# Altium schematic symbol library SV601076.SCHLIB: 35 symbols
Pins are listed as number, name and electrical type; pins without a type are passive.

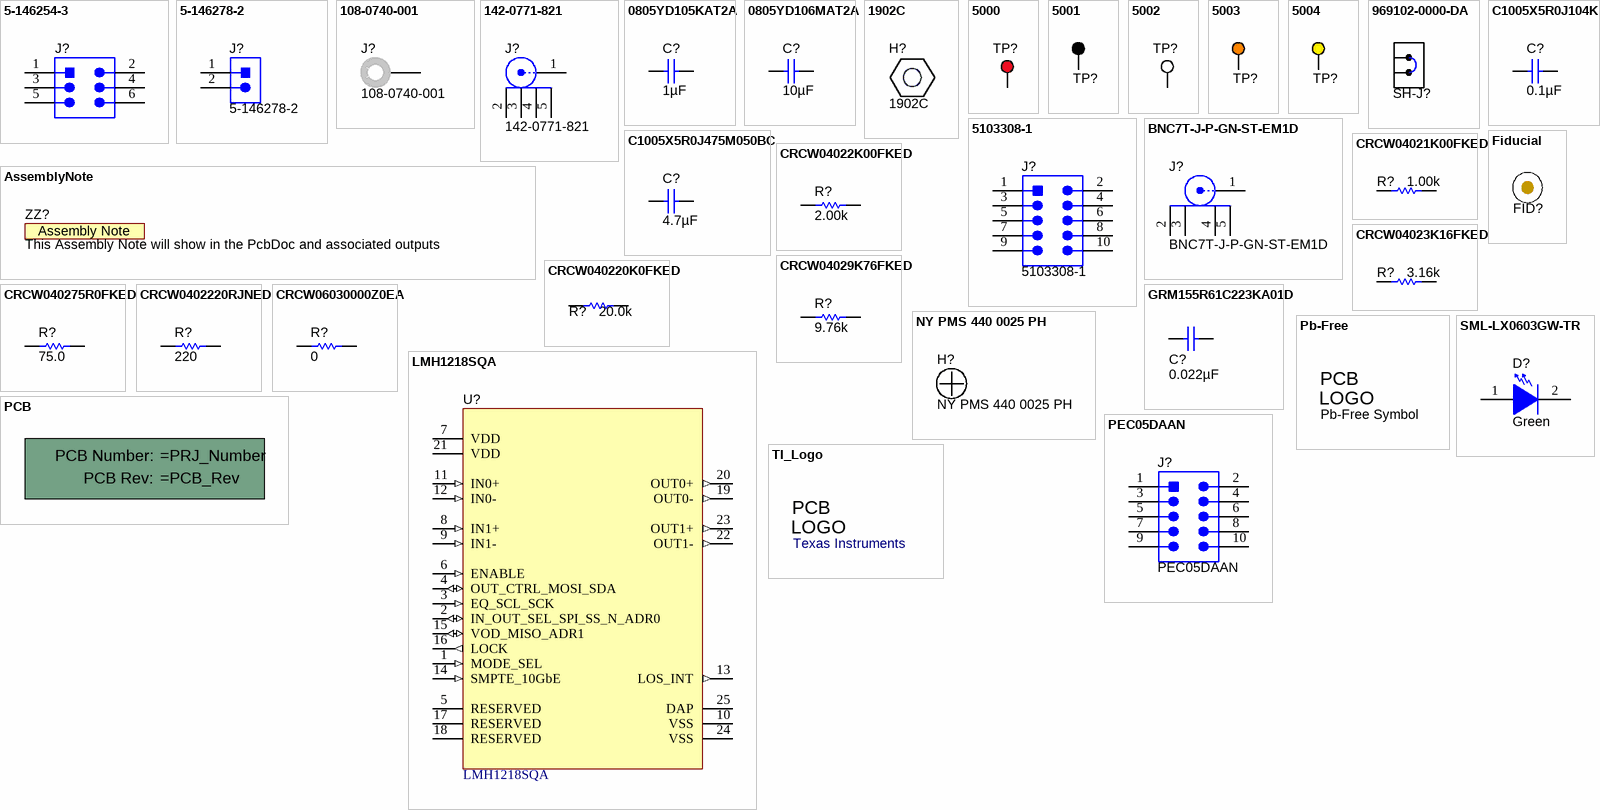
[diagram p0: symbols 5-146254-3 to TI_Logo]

## 5-146254-3
designator J?  (value not drawn)
Header, 100mil, 3x2, Tin, TH; Manufacturer: TE Connectivity; SymbolCreator: a0412235; U/M: EA
footprint TE_5-146254-3
pins: 1, 2, 3, 4, 5, 6

## 5-146278-2
designator J?
Header, 100mil, 2x1, Tin, TH; Manufacturer: TE Connectivity; SymbolCreator: a0412235; U/M: EA
footprint TE_5-146278-2
pins: 1, 2
1 alternate drawing of the same symbol

## 108-0740-001
designator J?
Standard Banana Jack, Uninsulated, 15A; Manufacturer: Emerson Network Power; SymbolCreator: a0412235; CompType: Connector; U/M: EA
footprint Johnson_108-0740-001
pins: 1

## 142-0771-821
designator J?
Connector, TH, End launch SMA 50 ohm; Manufacturer: Emerson Network Power; SymbolCreator: X0208326; U/M: EA
footprint Emerson_142-0771-821
pins: 1, 2, 3, 4, 5

## 0805YD105KAT2A
designator C?  ValueDisplayed: 1µF  (hidden comment: 0805YD105KAT2A)
CAP, CERM, 1uF, 16V, +/-10%, X5R, 0805; Manufacturer: AVX; Polarized: N; CompType: Capacitor; U/M: EA; Cap_F: 0.000001; Tolerance_%: 10; ESR_Ohm: 0.012; Value1: 0.012 ohm; VDC_V: 16; TaMin_C: -55; TaMax_C: 85; Cap_Case: 0805
signal-integrity model Cap
simulation model Cap
footprint 0805_HV
footprint 0805
footprint 0805M
footprint 0805L
pins: 1, 2

## 0805YD106MAT2A
designator C?  ValueDisplayed: 10µF  (hidden comment: 0805YD106MAT2A)
CAP, CERM, 10uF, 16V, +/-20%, X5R, 0805; Manufacturer: AVX; Polarized: N; CompType: Capacitor; U/M: EA; Cap_F: 0.00001; Tolerance_%: 20; Value1: Unknown; VDC_V: 16; TaMin_C: -55; TaMax_C: 85; Cap_Case: 0805
signal-integrity model Cap
simulation model Cap
footprint 0805_HV
footprint 0805
footprint 0805M
footprint 0805L
pins: 1, 2

## 1902C
designator H?
Standoff, Hex, 0.5"L #4-40 Nylon; Manufacturer: Keystone; CompType: Hardware; SymbolCreator: a0412235
footprint Keystone_1902C

## 5000
designator TP?  (value not drawn)
Test Point, Miniature, Red, TH; Manufacturer: Keystone; CompType: Test Point Loop; U/M: EA
footprint Keystone5000
pins: 1

## 5001
designator TP?  (value not drawn)
Test Point, Miniature, Black, TH; Manufacturer: Keystone; CompType: Test Point Loop; U/M: EA
footprint Keystone5001
pins: 1

## 5002
designator TP?  (value not drawn)
Test Point, Miniature, White, TH; Manufacturer: Keystone; CompType: Test Point Loop; U/M: EA
footprint Keystone5002
pins: 1

## 5003
designator TP?  (value not drawn)
Test Point, Miniature, Orange, TH; Manufacturer: Keystone; CompType: Test Point Loop; U/M: EA
footprint Keystone5003
pins: 1

## 5004
designator TP?  (value not drawn)
Test Point, Miniature, Yellow, TH; Manufacturer: Keystone; CompType: Test Point Loop; U/M: EA
footprint Keystone5004
pins: 1

## 969102-0000-DA
designator SH-J?  (value not drawn)
Shunt, 100mil, Gold plated, Black; Manufacturer: 3M; Alternate Manufacturer: Samtec; Alternate PartNumber: SNT-100-BK-G; Value: 1x2; Note: You can "mate" this to a header by matching the designator.  i.e. use SH-J3 for header J3
footprint SNT-100-BK-G

## 5103308-1
designator J?
Header (shrouded), 100mil, 5x2, Gold, TH; Manufacturer: TE Connectivity; SymbolCreator: a0412235; U/M: EA
footprint CONN_5103308-1
pins: 1, 2, 3, 4, 5, 6, 7, 8, 9, 10

## AssemblyNote
designator ZZ?, comment This Assembly Note will show in the PcbDoc and associated outputs  (no BOM)
SymbolCreator: codlsc
footprint AssemblyNote

## BNC7T-J-P-GN-ST-EM1D
designator J?
Connector, BNC Edge Mount, SMD; Manufacturer: Samtec; SymbolCreator: Altium; U/M: EA
footprint SAMTEC_BNC7T-J-P-GN-ST-EM1D
pins: 1, 2, 3, 4, 5

## C1005X5R0J104K
designator C?  ValueDisplayed: 0.1µF  (hidden comment: C1005X5R0J104K)
CAP, CERM, 0.1uF, 6.3V, +/-10%, X5R, 0402; Manufacturer: TDK; Polarized: N; CompType: Capacitor; U/M: EA; Cap_F: 0.0000001; Tolerance_%: 10; ESR_Ohm: 0.0186; Value1: 0.0186 ohm; VDC_V: 6.3; TaMin_C: -55; TaMax_C: 85; Cap_Case: 0402
signal-integrity model Cap
simulation model Cap
footprint 0402
footprint 0402M
footprint 0402L
footprint 0402S
pins: 1, 2

## C1005X5R0J475M050BC
designator C?  ValueDisplayed: 4.7µF  (hidden comment: C1005X5R0J475M050BC)
CAP, CERM, 4.7uF, 6.3V, +/-20%, X5R, 0402; Manufacturer: TDK; Polarized: N; CompType: Capacitor; U/M: EA; Cap_F: 0.0000047; Tolerance_%: 20; Value1: Unknown; VDC_V: 6.3; TaMin_C: -55; TaMax_C: 85; Cap_Case: 0402
signal-integrity model Cap
simulation model Cap
footprint 0402
footprint 0402M
footprint 0402L
footprint 0402S
pins: 1, 2

## CRCW04021K00FKED
designator R?  value 1.00k  (hidden comment: CRCW04021K00FKED)
RES, 1.00k ohm, 1%, 0.063W, 0402; Manufacturer: Vishay-Dale; CompType: Resistor; Res_ohm: 1000; Value_Code: 1k00; Tolerance_%: 1; Power_W: 0.063; VDC_V: 50; TempCo: 100 ppm/C; EIA_Code: E96; U/M: EA
signal-integrity model Resistor
simulation model Resistor
footprint 0402
footprint 0402M
footprint 0402L
footprint 0402S
pins: 1, 2

## CRCW04022K00FKED
designator R?  value 2.00k  (hidden comment: CRCW04022K00FKED)
RES, 2.00k ohm, 1%, 0.063W, 0402; Manufacturer: Vishay-Dale; CompType: Resistor; Res_ohm: 2000; Value_Code: 2k00; Tolerance_%: 1; Power_W: 0.063; VDC_V: 50; TempCo: 100 ppm/C; EIA_Code: E96; U/M: EA
signal-integrity model Resistor
simulation model Resistor
footprint 0402
footprint 0402M
footprint 0402L
footprint 0402S
pins: 1, 2

## CRCW04023K16FKED
designator R?  value 3.16k  (hidden comment: CRCW04023K16FKED)
RES, 3.16k ohm, 1%, 0.063W, 0402; Manufacturer: Vishay-Dale; CompType: Resistor; Res_ohm: 3160; Value_Code: 3k16; Tolerance_%: 1; Power_W: 0.063; VDC_V: 50; TempCo: 100 ppm/C; EIA_Code: E96; U/M: EA
signal-integrity model Resistor
simulation model Resistor
footprint 0402
footprint 0402M
footprint 0402L
footprint 0402S
pins: 1, 2

## CRCW04029K76FKED
designator R?  value 9.76k  (hidden comment: CRCW04029K76FKED)
RES, 9.76k ohm, 1%, 0.063W, 0402; Manufacturer: Vishay-Dale; CompType: Resistor; Res_ohm: 9760; Value_Code: 9k76; Tolerance_%: 1; Power_W: 0.063; VDC_V: 50; TempCo: 100 ppm/C; EIA_Code: E96; U/M: EA
signal-integrity model Resistor
simulation model Resistor
footprint 0402
footprint 0402M
footprint 0402L
footprint 0402S
pins: 1, 2

## CRCW040220K0FKED
designator R?  value 20.0k  (hidden comment: CRCW040220K0FKED)
RES, 20.0k ohm, 1%, 0.063W, 0402; Manufacturer: Vishay-Dale; CompType: Resistor; Res_ohm: 20000; Value_Code: 20k0; Tolerance_%: 1; Power_W: 0.063; VDC_V: 50; TempCo: 100 ppm/C; EIA_Code: E96; U/M: EA
signal-integrity model Resistor
simulation model Resistor
footprint 0402
footprint 0402M
footprint 0402L
footprint 0402S
pins: 1, 2

## CRCW040275R0FKED
designator R?  value 75.0  (hidden comment: CRCW040275R0FKED)
RES, 75.0 ohm, 1%, 0.063W, 0402; Manufacturer: Vishay-Dale; CompType: Resistor; Res_ohm: 75; Value_Code: 75R0; Tolerance_%: 1; Power_W: 0.063; VDC_V: 50; TempCo: 100 ppm/C; EIA_Code: E96; U/M: EA
signal-integrity model Resistor
simulation model Resistor
footprint 0402
footprint 0402M
footprint 0402L
footprint 0402S
pins: 1, 2

## CRCW0402220RJNED
designator R?  value 220  (hidden comment: CRCW0402220RJNED)
RES, 220 ohm, 5%, 0.063W, 0402; Manufacturer: Vishay-Dale; CompType: Resistor; Value_Code: 220R; Tolerance_%: 5; Power_W: 0.063; VDC_V: 50; TempCo: 200 ppm/C; EIA_Code: E24; U/M: EA
signal-integrity model Resistor
simulation model Resistor
footprint 0402
footprint 0402M
footprint 0402L
footprint 0402S
pins: 1, 2

## CRCW06030000Z0EA
designator R?  ValueDisplayed: 0  (hidden comment: CRCW06030000Z0EA)
RES, 0, 5%, 0.1 W, 0603; Manufacturer: Vishay-Dale; CompType: Resistor; Value: 0; Value_Code: 0000; Tolerance_%: 5; Power_W: 0.1; Value2: 0.1W; VDC_V: 75; TempCo: 200 ppm/C; EIA_Code: E24; U/M: EA
signal-integrity model Resistor
simulation model Resistor
footprint 0603
footprint 0603M
footprint 0603L
footprint 0603_HV
footprint 0603S
pins: 1, 2

## Fiducial
designator FID?  (value not drawn)
Fiducial mark.  There is nothing to buy or mount.; SymbolCreator: codlsc
footprint Fiducial10-30
footprint Fiducial10-20
footprint Fiducial15-30
footprint Fiducial20-40
footprint Fiducial6.4-20
footprint Fiducial10-30_Panel

## GRM155R61C223KA01D
designator C?  ValueDisplayed: 0.022µF  (hidden comment: GRM155R61C223KA01D)
CAP, CERM, 0.022uF, 16V, +/-10%, X5R, 0402; Manufacturer: MuRata; Polarized: N; CompType: Capacitor; U/M: EA; Cap_F: 0.000000022; Tolerance_%: 10; Value1: Unknown; VDC_V: 16; TaMin_C: -55; TaMax_C: 85; Cap_Case: 0402
signal-integrity model Cap
simulation model Cap
footprint 0402
footprint 0402M
footprint 0402L
footprint 0402S
pins: 1, 2

## LMH1218SQA
designator U?
Ultra HD Low-Power SDI Reclocker and Cable Driver, RTW0024A; Alternate Manufacturer: None; Manufacturer: Texas Instruments; SymbolCreator: Altium; CompType: IC; U/M: EA
footprint RTW0024A
pins: 1 MODE_SEL (in), 2 IN_OUT_SEL_SPI_SS_N_ADR0 (io), 3 EQ_SCL_SCK (in), 4 OUT_CTRL_MOSI_SDA (io), 5 RESERVED "No Connect", 6 ENABLE (in), 7 VDD (power) "2.5V +/- 5%", 8 IN1+ (in) "non-inverting CML-compatible differential inputs. An on-chip 100 Ohm terminating resistor connects P to N. Input require AC coupling.", 9 IN1- (in) "Inverting CML-compatible differential inputs. An on-chip 100 Ohm terminating resistor connects P to N. Input require AC coupling.", 10 VSS (power), 11 IN0+ (in) "non-inverting CML-compatible differential inputs. An on-chip 100 Ohm terminating resistor connects P to N. Input require AC coupling.", 12 IN0- (in) "Inverting CML-compatible differential inputs. An on-chip 100 Ohm terminating resistor connects P to N. Input require AC coupling.", 13 LOS_INT (out), 14 SMPTE_10GbE (in) "No Connect", 15 VOD_MISO_ADR1 (io), 16 LOCK (out), 17 RESERVED "No Connect", 18 RESERVED "No Connect", 19 OUT0- (out) "Inverting 75 Ohm outputs. Outputs require AC coupling", 20 OUT0+ (out) "non-inverting 75 Ohm outputs. Outputs require AC coupling", 21 VDD (power) "2.5V +/- 5%", 22 OUT1- (out) "Inverting CML-compatible differential outputs. An on-chip 100 Ohm terminating resistor connects P to N. Outputs require AC coupling", 23 OUT1+ (out) "non-inverting CML-compatible differential outputs. An on-chip 100 Ohm terminating resistor connects P to N. Outputs require AC coupling", 24 VSS (power), 25 DAP (power) "Exposed DAP, connect to GND"

## NY PMS 440 0025 PH
designator H?
Machine Screw, Round, #4-40 x 1/4, Nylon, Philips panhead; Manufacturer: B&F Fastener Supply; CompType: Hardware; SymbolCreator: codlsc; U/M: EA
footprint NY PMS 440 0025 PH
footprint NY PMS 440 0025 PH_3Donly

## Pb-Free
designator Logo?, comment Pb-Free Symbol  (no BOM)
SymbolCreator: a0412235
footprint Pb-Free_Overlay_Medium
footprint Pb-Free_Overlay_Small

## PCB
designator !PCB?, comment Printed Circuit Board  (value not drawn)  (mechanical)
Manufacturer: Any; SymbolCreator: a0412235; CompType: PCB
1 alternate drawing of the same symbol

## PEC05DAAN
designator J?
Header, 100mil, 5x2, Tin, TH; Manufacturer: Sullins Connector Solutions; SymbolCreator: a0412235; U/M: EA
footprint CONN_PEC05DAAN
pins: 1, 2, 3, 4, 5, 6, 7, 8, 9, 10

## SML-LX0603GW-TR
designator D?  value Green  (hidden comment: SML-LX0603GW-TR)
LED, Green, SMD; Manufacturer: Lumex; Vf_V: 2.2; Value2: 2.2V; Io_A: 0.02; Tjmax_C: 85; Value1: W; U/M: EA
signal-integrity model Diode
footprint LED_SML-LX0603GW
pins: 1 A, 2 K

## TI_Logo
designator Logo?, comment Texas Instruments  (no BOM)
Texas Instrument Corporate Signature; SymbolCreator: a0412235
footprint TI_Stacked_SolderMask_Medium
footprint TI_Stacked_SolderMask_Medium_Vertical
footprint TI_Stacked_SolderMask_Small
footprint TI_Stacked_SolderMask_Small_Vertical
footprint TI_Stacked_Overlay_Medium
footprint TI_Stacked_Overlay_Medium_Vertical
footprint TI_Stacked_Overlay_Small
footprint TI_Stacked_Overlay_Small_Vertical
footprint TI_Horizontal_SolderMask_Small
footprint TI_Horizontal_Overlay_Medium
footprint TI_Horizontal_Overlay_Small
footprint TI_Symbol_SolderMask_Medium
footprint TI_Symbol_SolderMask_Small
footprint TI_Symbol_Overlay_Medium
footprint TI_Symbol_Overlay_Small
footprint TI_Horizontal_SolderMask_Medium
